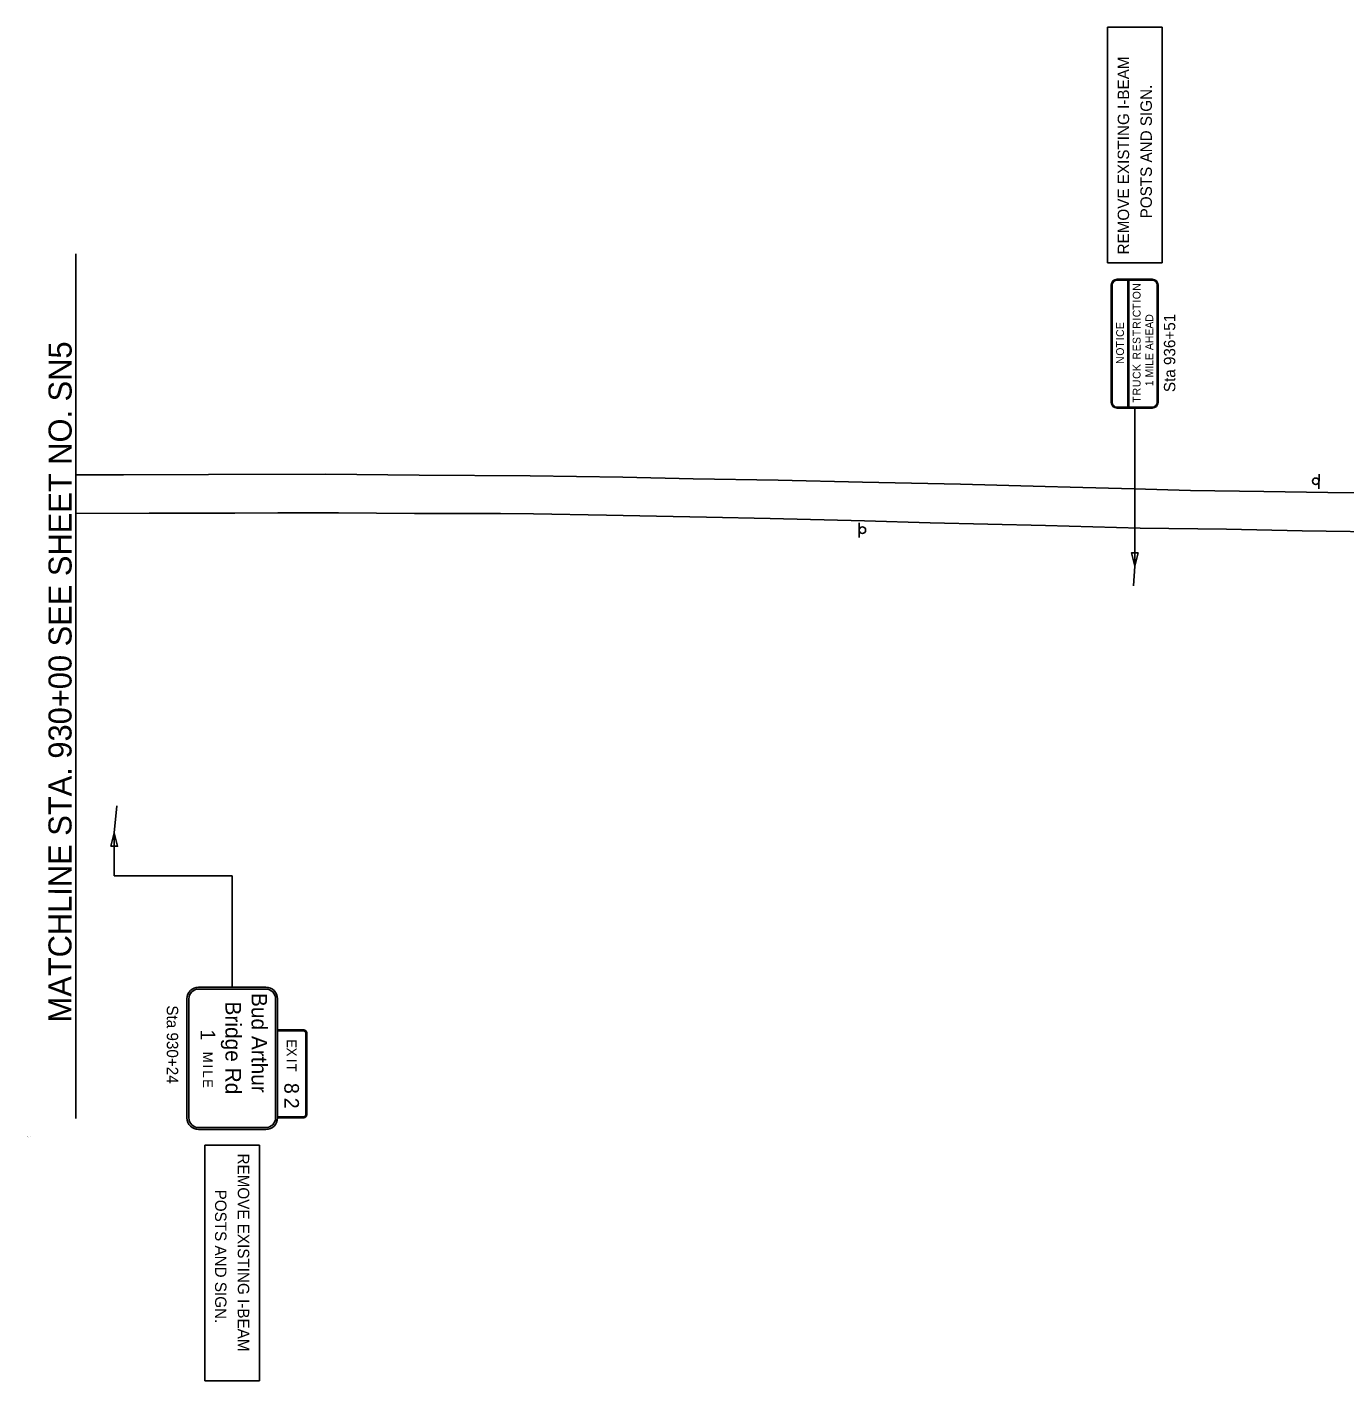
# Model space of a CAD drawing. Extents: x 1738774 to 1740361, y 1169069 to 1169940.
# Drawn here: x 1738774 to 1739584, y 1169069 to 1169901 of the extents above; entities that cross this region are included whole.
import ezdxf

# ---------------------------------------------------------------- set-up
doc = ezdxf.new("R2010")
doc.units = 0
for name, color, linetype in [('Default', 7, 'Continuous'), ('RD_EX_Road', 7, 'Continuous'), ('RD_SHT_MatchLine', 7, 'Continuous'), ('RD_SHT_TX', 7, 'Continuous'), ('SN_P_Signs', 7, 'Continuous')]:
    doc.layers.add(name, color=color, linetype=linetype)

msp = doc.modelspace()

# ---------------------------------------------------------------- linework, layer by layer
at = {"layer": 'RD_EX_Road'}
for points in [[(1739613.55, 1169614.28), (1739573.57, 1169614.73), (1739534.13, 1169615.31), (1739489.02, 1169616.06), (1739454.41, 1169617.03), (1739415.16, 1169618.12), (1739399.67, 1169618.48), (1739347.78, 1169619.97), (1739287.42, 1169621.22), (1739235.62, 1169622.45), (1739183.22, 1169623.28), (1739140.01, 1169624.17), (1739083.13, 1169625.09), (1739014.85, 1169625.37), (1738957.27, 1169625.99), (1738885.27, 1169625.76), (1738832.97, 1169625.64), (1738803.73, 1169625.65)], [(1739617.01, 1169590.32), (1739557.78, 1169591.25), (1739511.32, 1169592.27), (1739458.23, 1169592.95), (1739399.97, 1169594.58), (1739329.13, 1169596.15), (1739288.65, 1169597.38), (1739230.67, 1169598.86), (1739191.49, 1169599.66), (1739130.06, 1169600.84), (1739085.21, 1169601.65), (1739064.77, 1169601.8), (1739011.89, 1169601.92), (1738965.16, 1169602.35), (1738927.94, 1169602.24), (1738901.56, 1169602.08), (1738848.83, 1169602.01), (1738803.73, 1169601.8)]]:
    msp.add_lwpolyline(points, dxfattribs=at)
at = {"layer": 'RD_SHT_MatchLine'}
msp.add_lwpolyline([(1738803.73, 1169229.9), (1738803.73, 1169494.04), (1738803.73, 1169761.51)], dxfattribs=at)
at = {"layer": 'SN_P_Signs'}
for p, q in [((1739437.99, 1169755.91), (1739437.99, 1169900.93)), ((1739437.99, 1169900.93), (1739471.61, 1169900.93)), ((1739471.61, 1169900.93), (1739471.61, 1169755.91)), ((1739471.61, 1169755.91), (1739437.99, 1169755.91)), ((1739450.6, 1169745.91), (1739451.2, 1169745.91)), ((1739451.2, 1169745.91), (1739465.6, 1169745.91)), ((1739451.2, 1169667.31), (1739451.2, 1169745.31)), ((1739451.2, 1169745.31), (1739465.6, 1169745.31)), ((1739451.2, 1169666.71), (1739450.6, 1169666.71)), ((1739465.6, 1169667.31), (1739451.2, 1169667.31)), ((1739465.6, 1169666.71), (1739451.2, 1169666.71)), ((1739454.8, 1169666.71), (1739454.8, 1169569.43)), ((1739568.06, 1169617.14), (1739568.19, 1169626.14)), ((1739285.36, 1169596.14), (1739285.32, 1169587.14)), ((1739454.05, 1169557.49), (1739454.8, 1169569.43)), ((1738827.2, 1169405.54), (1738829.02, 1169422.16)), ((1738827.2, 1169379.21), (1738827.2, 1169405.54)), ((1738827.2, 1169379.21), (1738899.87, 1169379.21)), ((1738899.87, 1169310.67), (1738899.87, 1169379.21)), ((1738926.52, 1169230.35), (1738926.52, 1169303.47)), ((1738927.72, 1169230.35), (1738927.72, 1169303.47)), ((1738883.06, 1169068.6), (1738883.06, 1169213.62)), ((1738883.06, 1169213.62), (1738916.68, 1169213.62)), ((1738916.68, 1169213.62), (1738916.68, 1169068.6)), ((1738916.68, 1169068.6), (1738883.06, 1169068.6))]:
    msp.add_line(p, q, dxfattribs=at)
for points in [[(1739440.4, 1169670.31), (1739440.4, 1169742.31)], [(1739441, 1169670.31), (1739441, 1169742.31)], [(1739444, 1169745.91), (1739450.6, 1169745.91)], [(1739444, 1169745.31), (1739450.6, 1169745.31)], [(1739450.6, 1169745.31), (1739450.6, 1169667.31)], [(1739468.6, 1169742.31), (1739468.6, 1169670.31)], [(1739469.2, 1169742.31), (1739469.2, 1169670.31)], [(1739450.6, 1169667.31), (1739444, 1169667.31)], [(1739450.6, 1169666.71), (1739444, 1169666.71)], [(1738920.52, 1169310.67), (1738879.22, 1169310.67)], [(1738920.52, 1169309.47), (1738879.22, 1169309.47)], [(1738872.02, 1169303.47), (1738872.02, 1169230.35)], [(1738873.22, 1169303.47), (1738873.22, 1169230.35)], [(1738943.92, 1169283.75), (1738927.72, 1169283.75), (1738927.72, 1169284.35), (1738943.92, 1169284.35)], [(1738945.12, 1169232.15), (1738945.12, 1169282.55)], [(1738945.72, 1169282.55), (1738945.72, 1169232.15)], [(1738879.22, 1169224.35), (1738920.52, 1169224.35)], [(1738943.92, 1169230.35), (1738927.72, 1169230.35), (1738927.72, 1169230.95)], [(1738927.72, 1169230.95), (1738943.92, 1169230.95)], [(1738879.22, 1169223.15), (1738920.52, 1169223.15)]]:
    msp.add_lwpolyline(points, dxfattribs=at)
for points in [[(1739456.85, 1169577.63), (1739454.8, 1169569.43), (1739452.75, 1169577.63)], [(1738825.29, 1169397.32), (1738827.25, 1169405.54), (1738829.39, 1169397.36)]]:
    msp.add_lwpolyline(points, close=True, dxfattribs=at)
for centre in [(1739566.1, 1169621.69), (1739287.36, 1169591.61)]:
    msp.add_circle(centre, 2, dxfattribs=at)
for centre, radius, start, end in [((1739444, 1169742.31), 3.6, 90, 180), ((1739444, 1169742.31), 3, 90, 180), ((1739465.6, 1169742.31), 3.6, 0, 90), ((1739465.6, 1169742.31), 3, 0, 90), ((1739444, 1169670.31), 3.6, 180, 270), ((1739444, 1169670.31), 3, 180, 270), ((1739465.6, 1169670.31), 3.6, 270, 0), ((1739465.6, 1169670.31), 3, 270, 0), ((1738879.22, 1169303.47), 7.2, 90, 180), ((1738879.22, 1169303.47), 6, 90, 180), ((1738920.52, 1169303.47), 7.2, 360, 90), ((1738920.52, 1169303.47), 6, 360, 90), ((1738943.92, 1169282.55), 1.8, 360, 90), ((1738943.92, 1169282.55), 1.2, 360, 90), ((1738943.92, 1169232.15), 1.2, 270, 360), ((1738943.92, 1169232.15), 1.8, 270, 360), ((1738879.22, 1169230.35), 7.2, 180, 270), ((1738879.22, 1169230.35), 6, 180, 270), ((1738920.52, 1169230.35), 7.2, 270, 360), ((1738920.52, 1169230.35), 6, 270, 360)]:
    msp.add_arc(centre, radius, start, end, dxfattribs=at)

# ---------------------------------------------------------------- texts
at = {"layer": 'Default'}
for s, height, p in [('Angle:  16.0848', 0.2083, (1738773.73, 1169218.56)), ('Align: A_I85', 0.2083, (1738773.73, 1169218.29)), ('Sheet: 6', 0.208, (1738773.73, 1169218.83))]:
    msp.add_text(s, height=height, dxfattribs=at).set_placement(p)
at = {"layer": 'RD_SHT_TX'}
msp.add_text('MATCHLINE STA. 930+00 SEE SHEET NO. SN5', height=14.1726, rotation=89.98556, dxfattribs=at).set_placement((1738801.04, 1169289))
at = {"layer": 'SN_P_Signs'}
for s, height, rotation, p in [('REMOVE EXISTING I-BEAM', 6.9998, 90.00008, (1739451.35, 1169761.14)), ('POSTS AND SIGN.', 6.9998, 90.00008, (1739465.35, 1169783.33)), ('N', 4.8, 90, (1739458.4, 1169738.82)), ('O', 4.8, 90, (1739458.4, 1169733.6)), ('I', 4.8, 90, (1739458.4, 1169731.54)), ('C', 4.8, 90, (1739458.4, 1169722.54)), ('T', 4.8, 90, (1739458.4, 1169727.03)), ('1 MILE AHEAD', 4.8, 90, (1739466.2, 1169680.18)), ('Sta 936+51', 7, 90.07059, (1739479.79, 1169676.5)), ('E', 4.8, 90, (1739448.2, 1169715.26)), ('E', 4.8, 90, (1739448.2, 1169715.26)), ('I', 4.8, 90, (1739458.4, 1169720.48)), ('R', 4.8, 90, (1739458.4, 1169715.42)), ('C', 4.8, 90, (1739448.2, 1169710.44)), ('C', 4.8, 90, (1739448.2, 1169710.44)), ('I', 4.8, 90, (1739448.2, 1169708.38)), ('I', 4.8, 90, (1739448.2, 1169708.38)), ('T', 4.8, 90, (1739448.2, 1169703.87)), ('T', 4.8, 90, (1739448.2, 1169703.87)), ('S', 4.8, 90, (1739458.4, 1169706.09)), ('T', 4.8, 90, (1739458.4, 1169710.9)), ('O', 4.8, 90, (1739448.2, 1169698.9)), ('O', 4.8, 90, (1739448.2, 1169698.9)), ('E', 4.8, 90, (1739458.4, 1169701.58)), ('R', 4.8, 90, (1739458.4, 1169696.51)), ('N', 4.8, 90, (1739448.2, 1169693.84)), ('N', 4.8, 90, (1739448.2, 1169693.84)), ('K', 4.8, 90, (1739458.4, 1169689.43)), ('C', 4.8, 90, (1739458.4, 1169684.62)), ('U', 4.8, 90, (1739458.4, 1169679.56)), ('R', 4.8, 90, (1739458.4, 1169674.5)), ('T', 4.8, 90, (1739458.4, 1169669.98)), ('Sta 930+24', 7, 270.00008, (1738859.65, 1169299.49)), ('Bridge Rd', 9.6, 270, (1738895.72, 1169301.87)), ('Bud Arthur', 9.6, 270, (1738911.75, 1169307.12)), ('1', 9, 270, (1738880.42, 1169284.73)), ('E', 6, 270, (1738933.42, 1169278.62)), ('M', 6, 270, (1738881.92, 1169270.98)), ('X', 6, 270, (1738933.42, 1169273.47)), ('I', 6, 270, (1738933.42, 1169266.65)), ('I', 6, 270, (1738881.92, 1169263.12)), ('L', 6, 270, (1738881.92, 1169259.53)), ('T', 6, 270, (1738933.42, 1169263.67)), ('E', 6, 270, (1738881.92, 1169254.1)), ('8', 9, 270, (1738931.92, 1169251.8)), ('2', 9, 270, (1738931.92, 1169242.7)), ('REMOVE EXISTING I-BEAM', 6.9998, 270.00008, (1738903.32, 1169208.39)), ('POSTS AND SIGN.', 6.9998, 270.00008, (1738889.32, 1169186.2))]:
    msp.add_text(s, height=height, rotation=rotation, dxfattribs=at).set_placement(p)

doc.saveas('drawing.dxf')
